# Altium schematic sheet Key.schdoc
size 297 x 209 mm; Symbol: Drawing-Symbol_A4; Company: 嘉立创EDA; Version: V1.0; Page Size: A4; @Project Name: A113 Android MircroPhone; @Page Count: 7; @Update Date: 2025-12-04; @Create Date: 2025-12-04; @Schematic Name: Schematic1; @Page No: 7; @Page Name: Key; @Create Time: 23:43:06; @Update Time: 23:43:18; Border: 1; Width: 1170; Height: 825; Region Start: 1; X Region Count: 6; Y Region Count: 4; Blade Width: 10; Title Block Position: 3; @Board Name: Board1; Device: Drawing-Symbol_A4
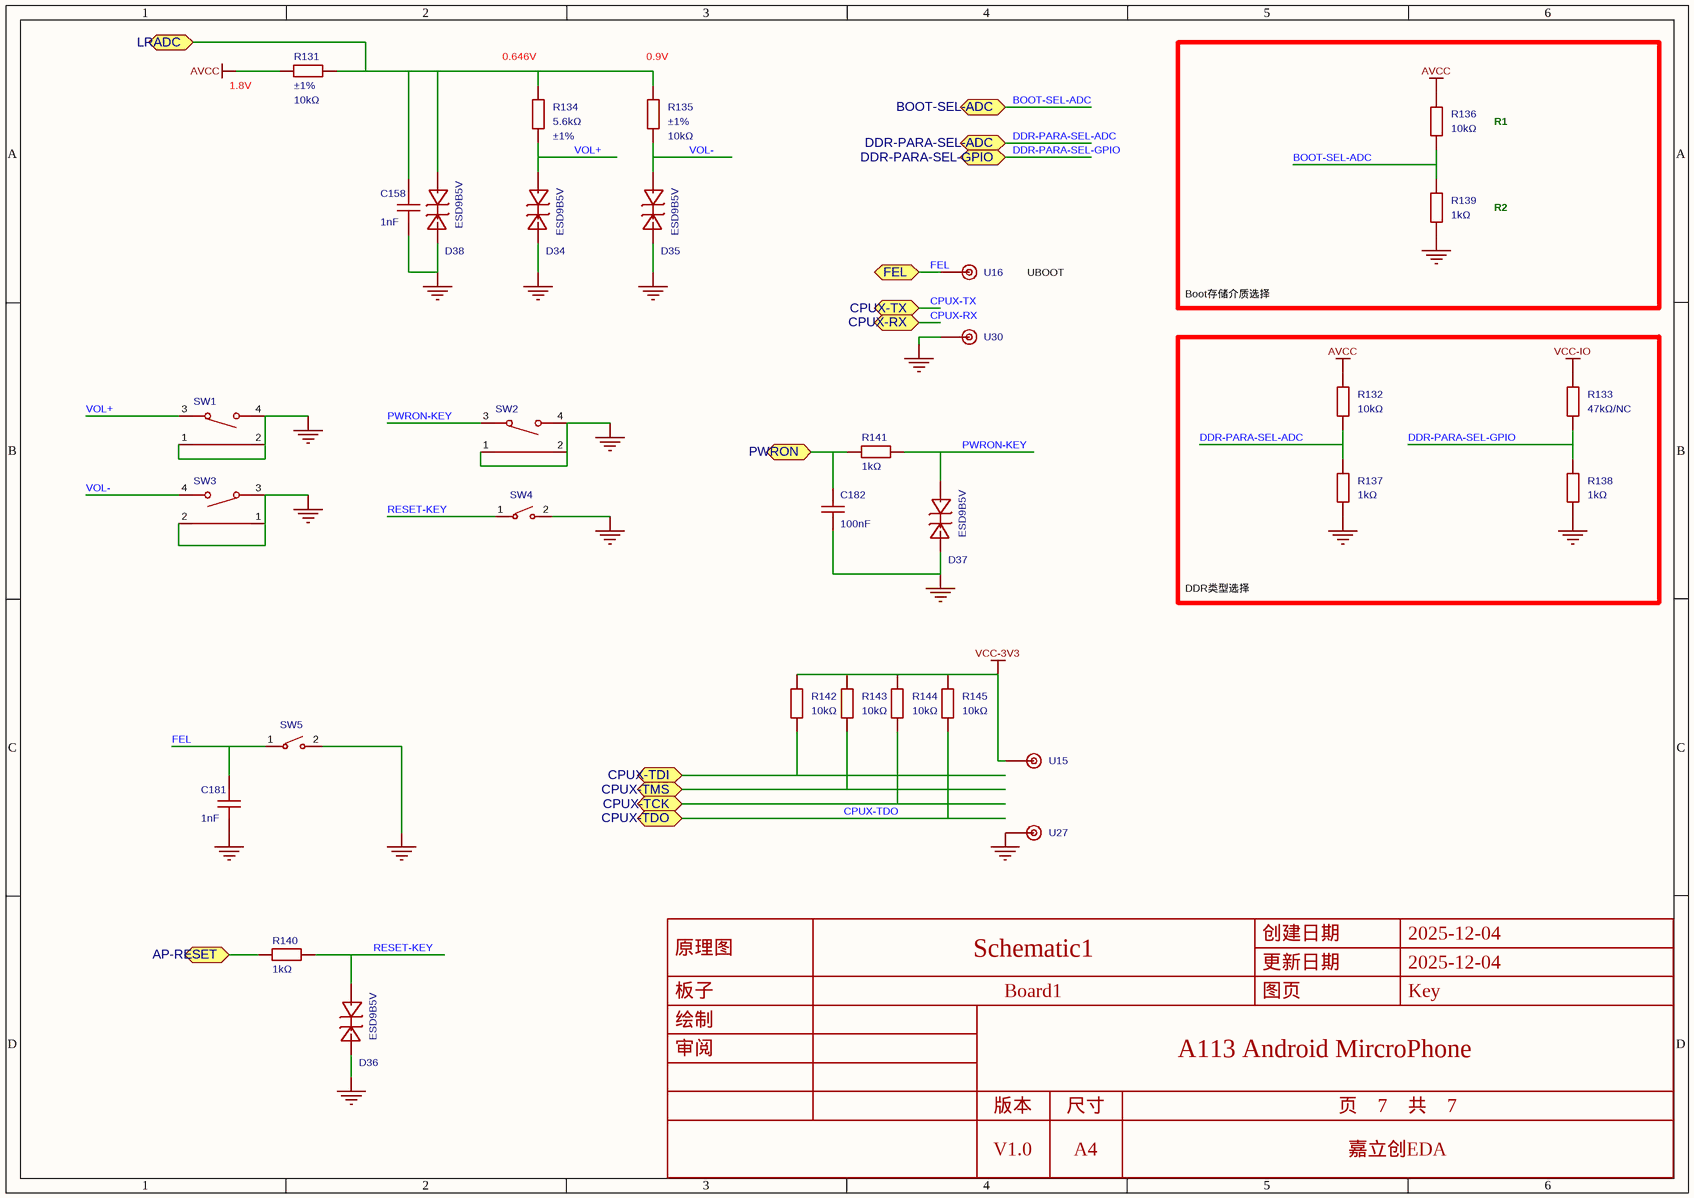
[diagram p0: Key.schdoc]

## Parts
C158  1nF  [C0402]
C181  1nF  [C0402]
C182  100nF  [C0402]
D34  ESD9B5V  [SOD-923_L0.8-W0.6-LS1.0-BI-1]
D35  ESD9B5V  [SOD-923_L0.8-W0.6-LS1.0-BI-1]
D36  ESD9B5V  [SOD-923_L0.8-W0.6-LS1.0-BI-1]
D37  ESD9B5V  [SOD-923_L0.8-W0.6-LS1.0-BI-1]
D38  ESD9B5V  [SOD-923_L0.8-W0.6-LS1.0-BI-1]
R131  Tolerance: ±1%  [R0402]  (hidden comment: 10kΩ)
R132  10kΩ  [R0402]
R133  47kΩ/NC  [R0402]
R134  Tolerance: ±1%  [R0402]  (hidden comment: 5.6kΩ)
R135  Tolerance: ±1%  [R0402]  (hidden comment: 10kΩ)
R136  10kΩ  [R0402]
R137  1kΩ  [R0402]
R138  1kΩ  [R0402]
R139  1kΩ  [R0402]
R140  1kΩ  [R0402]
R141  1kΩ  [R0402]
R142  10kΩ  [R0402]
R143  10kΩ  [R0402]
R144  10kΩ  [R0402]
R145  10kΩ  [R0402]
SW1  TS24CA  [SW-SMD_TS24CA]  (value not drawn)
SW2  TS24CA  [SW-SMD_TS24CA]  (value not drawn)
SW3  TS24CA  [SW-SMD_TS24CA]  (value not drawn)
SW4  TS-1088R-02026  [SW-SMD_L3.9-W3.0-P4.45]  (value not drawn)
SW5  TS-1088R-02026  [SW-SMD_L3.9-W3.0-P4.45]  (value not drawn)
U15  测试焊盘  [焊盘]  (value not drawn)
U16  测试焊盘  [焊盘]  (value not drawn)
U27  测试焊盘  [焊盘]  (value not drawn)
U30  测试焊盘  [焊盘]  (value not drawn)

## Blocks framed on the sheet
DDR类型选择: R132 R133 R137 R138

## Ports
AP-RESET (bidir), BOOT-SEL-ADC (bidir), CPUX-RX (bidir), CPUX-TCK (bidir), CPUX-TDI (bidir), CPUX-TDO (bidir), CPUX-TMS (bidir), CPUX-TX (bidir), DDR-PARA-SEL-ADC (bidir), DDR-PARA-SEL-GPIO (bidir), FEL (bidir), LRADC (bidir), PWRON (bidir)

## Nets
AVCC: R131.2 R132.2 R136.2
GND: C158.1 C181.1 C182.2 D34.1(C) D35.1(C) D36.1(C) D37.1(C) D38.1(C) R137.1 R138.1 R139.1 SW1.1 SW1.2 SW1.4 SW2.1 SW2.2 SW2.4 SW3.1 SW3.2 SW3.3 SW4.2 SW5.2 U27.1 U30.1
VCC-3V3: R142.2 R143.2 R144.2 R145.2 U15.1
VCC-IO: R133.2
AP-RESET: R140.1 ; port AP-RESET
BOOT-SEL-ADC: R136.1 R139.2 ; port BOOT-SEL-ADC
CPUX-TCK: R144.1 ; port CPUX-TCK
CPUX-TDI: R142.1 ; port CPUX-TDI
CPUX-TDO: R145.1 ; port CPUX-TDO
CPUX-TMS: R143.1 ; port CPUX-TMS
DDR-PARA-SEL-ADC: R132.1 R137.2 ; port DDR-PARA-SEL-ADC
DDR-PARA-SEL-GPIO: R133.1 R138.2 ; port DDR-PARA-SEL-GPIO
FEL: C181.2 SW5.1 U16.1 ; port FEL
LRADC: C158.2 D38.2(A) R131.1 R134.2 R135.1 ; port LRADC
PWRON: C182.1 R141.1 ; port PWRON
PWRON-KEY: D37.2(A) R141.2 SW2.3
RESET-KEY: D36.2(A) R140.2 SW4.1
VOL+: D34.2(A) R134.1 SW1.3
VOL-: D35.2(A) R135.2 SW3.4

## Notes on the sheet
- (near R134) 0.646V
- (near R135) 0.9V
- (near R131) 1.8V
- R1
- R2
- UBOOT
- Boot存储介质选择

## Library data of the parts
C158 C181 = CL05C102JB5NNNC: 容值:1nF;精度:±5%;额定电压:50V;材质(温度系数):C0G;; Manufacturer: SAMSUNG(三星); AddInBom: yes; ModelId: 36a51122f27c49738f86b3bfa98863e0; ModelName: C0402_L1.0-W0.5-H0.5; ModelTransform: 39.37,19.685,0,0,0,0,0,0,0; Tolerance: ±5%; Voltage Rated: 50V; Temperature Coefficient: C0G
C182 = CL05B104KO5NNNC: 容值:100nF;精度:±10%;额定电压:16V;材质(温度系数):X7R;; Manufacturer: SAMSUNG(三星); AddInBom: yes; ModelId: 36a51122f27c49738f86b3bfa98863e0; ModelName: C0402_L1.0-W0.5-H0.5; ModelTransform: 39.37,19.685,0,0,0,0,0,0,0; Tolerance: ±10%; Voltage Rated: 16V; Temperature Coefficient: X7R
D34-D38 = ESD9B5V: Manufacturer: TECH PUBLIC(台舟); AddInBom: yes; ModelId: 2f595e76c437472fa7f031dc65d7fe13; ModelTransform: 39.37,23.622,0,0,0,0,-0.005,0,0
R131 R135 = 0402WGF1002TCE: 电阻类型:厚膜电阻;阻值:10kΩ;精度:±1%;功率:62.5mW;; Manufacturer: UNI-ROYAL(厚声); Symbol: RC0402FR-0710KL; AddInBom: yes; ModelId: 671aefced39d4c318694bba8bd8efd39; ModelName: R0402_L1.0-W0.5-H0.5; ModelTransform: 39.37,19.685,0,0,0,0,0,0.0005,0; Power(Watts): 62.5mW; Temperature Coefficient: ±100ppm/℃; Overload Voltage (Max): 50V
R132 R136 = RC0402FR-0710KL: 电阻类型:厚膜电阻;阻值:10kΩ;精度:±1%;功率:62.5mW;; Manufacturer: YAGEO(国巨); AddInBom: yes; ModelId: 671aefced39d4c318694bba8bd8efd39; ModelName: R0402_L1.0-W0.5-H0.5; ModelTransform: 39.37,19.685,0,0,0,0,0,0.0005,0; Tolerance: ±1%; Power(Watts): 62.5mW; Temperature Coefficient: ±100ppm/℃; Overload Voltage (Max): 50V
R133 = RC0402FR-0747KL: 电阻类型:厚膜电阻;阻值:47kΩ;精度:±1%;功率:62.5mW;; Manufacturer: YAGEO(国巨); Symbol: 0402WGF4702TCE; Standardization Check: false; AddInBom: yes; ModelId: 671aefced39d4c318694bba8bd8efd39; ModelName: R0402_L1.0-W0.5-H0.5; ModelTransform: 39.37,19.685,0,0,0,0,0,0.0005,0; Tolerance: ±1%; Power(Watts): 62.5mW; Temperature Coefficient: ±100ppm/℃; Overload Voltage (Max): 50V
R134 = RC0402FR-075K6L: 电阻类型:厚膜电阻;阻值:5.6kΩ;精度:±1%;功率:62.5mW;; Manufacturer: YAGEO(国巨); AddInBom: yes; ModelId: 671aefced39d4c318694bba8bd8efd39; ModelName: R0402_L1.0-W0.5-H0.5; ModelTransform: 39.37,19.685,0,0,0,0,0,0.0005,0; Power(Watts): 62.5mW; Temperature Coefficient: ±100ppm/℃; Overload Voltage (Max): 50V
R137-R141 = AC0402FR-071KL: 电阻类型:厚膜电阻;阻值:1kΩ;精度:±1%;功率:62.5mW;; Manufacturer: YAGEO(国巨); AddInBom: yes; ModelId: 671aefced39d4c318694bba8bd8efd39; ModelName: R0402_L1.0-W0.5-H0.5; ModelTransform: 39.37,19.685,0,0,0,0,0,0.0005,0; Tolerance: ±1%; Power(Watts): 62.5mW; Temperature Coefficient: ±100ppm/℃; Overload Voltage (Max): 50V
R142-R145 = 0402WGF1002TCE: 电阻类型:厚膜电阻;阻值:10kΩ;精度:±1%;功率:62.5mW;; Manufacturer: UNI-ROYAL(厚声); Symbol: RC0402FR-0710KL; AddInBom: yes; ModelId: 671aefced39d4c318694bba8bd8efd39; ModelName: R0402_L1.0-W0.5-H0.5; ModelTransform: 39.37,19.685,0,0,0,0,0,0.0005,0; Tolerance: ±1%; Power(Watts): 62.5mW; Temperature Coefficient: ±100ppm/℃; Overload Voltage (Max): 50V
SW1-SW3 = TS24CA: 触点电流:50mA;额定电压(DC):12V;电路结构:单刀单掷;安装方式:卧贴;带灯:-;机械寿命:-;; Manufacturer: SHOU HAN(首韩); AddInBom: yes; ModelId: b2de6e3973c24e28b5c55d180348ee9a; ModelTransform: 179.134,141.732,0,0,0,0,0.003,44.293,-15.748; Contact Current: 50mA; Voltage Rating (DC): 12V; Circuit: 单刀单掷; Actuator Style: 矩形按钮; Switch Length: 4.55mm; Switch Width: 1.8mm; Switch Height: 3.5mm
SW4 SW5 = TS-1088R-02026: 触点电流:50mA;额定电压(DC):12V;电路结构:单刀单掷;安装方式:立贴;带灯:-;机械寿命:-;; Manufacturer: XUNPU(讯普); AddInBom: yes; ModelId: b26698b69f274ffabef8a26c7d0e5dd1; ModelName: SW-SMD_L3.9-W2.9-H2.0-LS4.8; ModelTransform: 188.976,114.174,0,0,0,0,0,0,0; Contact Current: 50mA; Voltage Rating (DC): 12V; Circuit: 单刀单掷; Actuator Style: 圆形按钮; Switch Length: 3.9mm; Switch Width: 2.93mm; Switch Height: 2mm
U15 U16 U27 U30 = 测试焊盘: Add into BOM: no; ConvertToPcb: yes; _: 3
